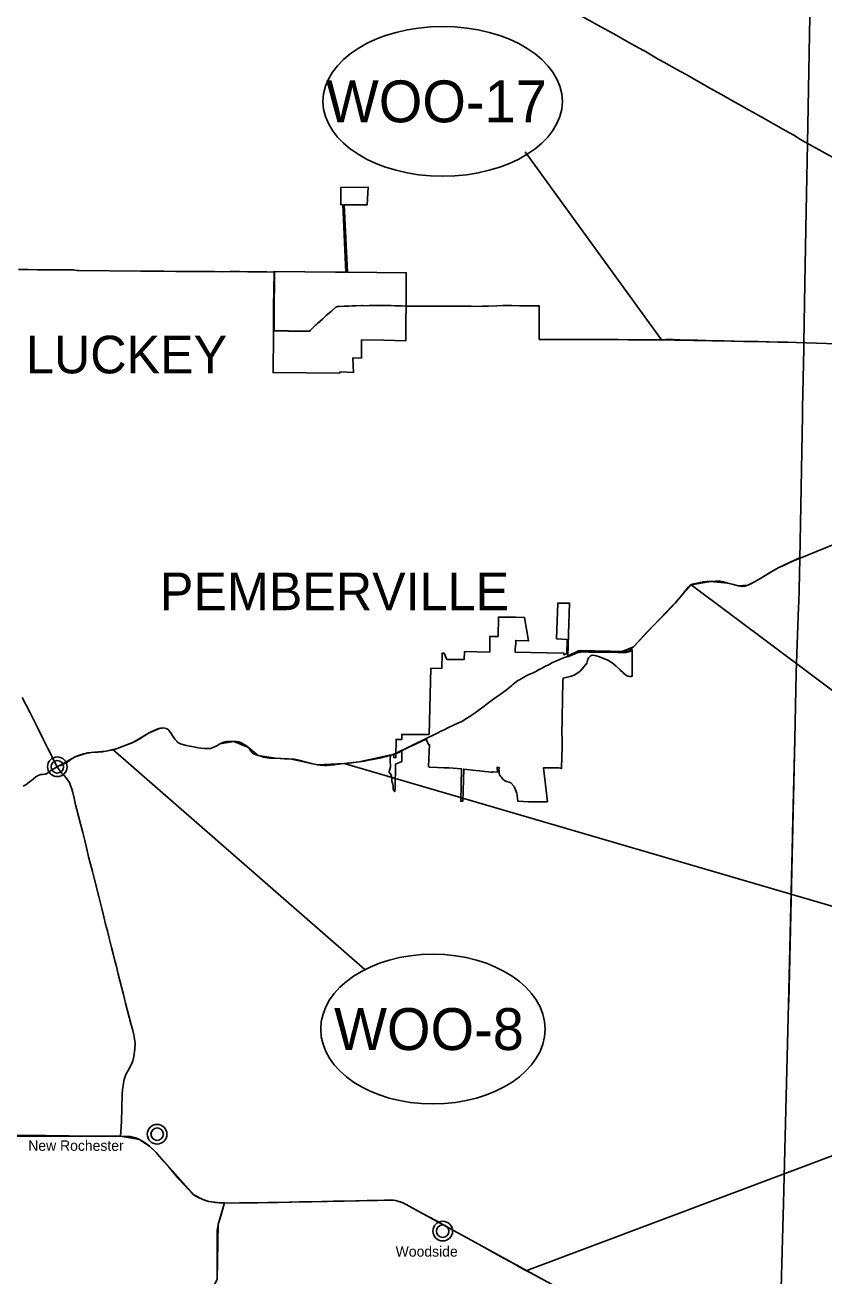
# Model space of a CAD drawing. Extents: x 0 to 851, y 0 to 440.
# Drawn here: x 370.6 to 424, y 193.8 to 277.3 of the extents above; entities that cross this region are included whole.
import ezdxf

# ---------------------------------------------------------------- set-up
doc = ezdxf.new("R2010")
doc.units = 0
for name, color, linetype in [('DV_X_Corp_Line', 7, 'Continuous'), ('GM_X_Corporation_Text', 7, 'Continuous'), ('GM_X_County', 7, 'Continuous'), ('GM_X_State_Route', 7, 'Continuous'), ('GM_X_US_Route', 7, 'Continuous'), ('RD_P_Fence', 7, 'Continuous'), ('SH_Data', 7, 'Continuous')]:
    doc.layers.add(name, color=color, linetype=linetype)

msp = doc.modelspace()

# ---------------------------------------------------------------- linework, layer by layer
at = {"layer": 'DV_X_Corp_Line'}
for points in [[(394.584, 256.284), (393.101, 256.305), (393.093, 255.09), (392.505, 255.087), (392.569, 254.126), (391.656, 254.156), (391.632, 254.084), (387.18, 254.12), (387.182, 254.462), (387.2, 256.317), (387.205, 256.909), (387.213, 257.407), (387.215, 258.013), (387.221, 258.556), (387.232, 259.629), (387.247, 260.871), (391.362, 260.823), (392.054, 260.821), (391.856, 265.336), (391.703, 265.333), (391.711, 266.479), (393.53, 266.511), (393.481, 265.331), (391.936, 265.327), (392.152, 260.82), (396.083, 260.785), (396.075, 258.565), (396.065, 257.568), (396.054, 256.234)], [(403.472, 226.002), (403.296, 226.461), (403.073, 226.7), (402.954, 226.741), (402.782, 226.8), (402.657, 226.868), (402.542, 226.952), (402.446, 227.075), (402.378, 227.159), (402.327, 227.248), (402.287, 227.357), (402.287, 227.479), (402.283, 227.593), (402.289, 227.702), (402.289, 227.737), (402.16, 227.742), (402.182, 227.412), (401.893, 227.448), (401.869, 227.435), (401.824, 227.422), (401.751, 227.417), (399.926, 227.616), (399.856, 225.475), (399.732, 225.476), (399.782, 227.631), (398.935, 227.703), (398.605, 227.712), (398.167, 227.737), (397.619, 227.753), (397.565, 227.806), (397.628, 229.258), (397.6, 229.229), (397.42, 229.61), (397.09, 229.456), (396.711, 229.281), (396.266, 229.076), (395.795, 228.858), (395.795, 228.131), (395.37, 227.945), (395.337, 226.34), (395.316, 226.114), (395.23, 226.243), (395.219, 226.304), (395.217, 226.403), (395.212, 226.488), (395.188, 226.582), (395.147, 226.75), (395.13, 226.792), (395.118, 226.862), (395.121, 226.964), (395.112, 227.056), (395.088, 227.153), (395.044, 227.252), (394.942, 227.409), (394.938, 227.456), (395.03, 227.77), (395.011, 228.213), (395.01, 228.253), (395.022, 228.541), (395.253, 228.62), (395.25, 228.386), (395.377, 228.382), (395.383, 228.671), (395.385, 228.738), (395.402, 229.351), (395.404, 229.602), (395.781, 229.598), (395.784, 229.934), (397.616, 229.94), (397.736, 234.359), (398.474, 234.351), (398.492, 235.373), (398.614, 235.369), (398.803, 234.952), (399.952, 234.941), (399.981, 235.488), (401.661, 235.432), (401.665, 235.65), (401.67, 236.49), (402.225, 236.485), (402.25, 237.778), (403.404, 237.762), (403.99, 237.742), (404.268, 236.182), (403.405, 236.223), (403.402, 236.024), (403.368, 235.628), (403.358, 235.438), (404.409, 235.409), (406.629, 235.372), (406.626, 235.252), (406.813, 235.346), (406.839, 236.291), (406.135, 236.314), (406.209, 238.708), (407.003, 238.71), (406.942, 236.669), (406.897, 235.121), (407.082, 235.203), (407.355, 235.327), (407.483, 235.381), (407.553, 235.406), (407.601, 235.419), (407.645, 235.432), (407.685, 235.434), (407.766, 235.442), (407.866, 235.445), (408.03, 235.445), (408.068, 235.445), (408.247, 235.442), (408.371, 235.441), (408.586, 235.438), (408.809, 235.436), (409.207, 235.434), (409.76, 235.431), (410.245, 235.421), (410.507, 235.416), (410.767, 235.419), (410.84, 235.428), (410.932, 235.451), (411.02, 235.487), (411.09, 235.527), (411.123, 235.551), (411.187, 235.607), (411.186, 235.43), (411.195, 234.342), (411.178, 233.827), (411.117, 233.811), (411.013, 233.811), (410.913, 233.833), (410.851, 233.849), (410.811, 233.869), (410.619, 234.016), (410.576, 234.07), (410.537, 234.116), (410.498, 234.14), (410.407, 234.216), (410.385, 234.254), (410.127, 234.502), (409.86, 234.713), (409.605, 234.867), (409.005, 235.126), (408.708, 235.202), (408.563, 235.233), (408.474, 235.218), (408.403, 235.183), (408.352, 235.14), (408.277, 235.047), (408.227, 234.949), (408.211, 234.902), (408.188, 234.799), (408.157, 234.709), (408.112, 234.623), (407.844, 234.314), (407.685, 234.137), (407.303, 233.902), (407.038, 233.803), (406.569, 233.686), (406.556, 233.498), (406.482, 229.852), (406.495, 229.836), (406.503, 229.82), (406.508, 229.797), (406.509, 229.763), (406.498, 229.081), (406.473, 227.728), (406.458, 227.654), (406.385, 227.691), (406.275, 227.702), (405.816, 227.703), (405.531, 227.701), (405.251, 227.7), (405.525, 225.438), (404.251, 225.44), (403.534, 225.482)]]:
    msp.add_lwpolyline(points, close=True, dxfattribs=at)
for centre, radius in [((372.759, 227.776), 0.658), ((372.759, 227.776), 0.417), ((379.429, 203.225), 0.658), ((379.429, 203.225), 0.417), ((398.524, 196.747), 0.658), ((398.524, 196.747), 0.417)]:
    msp.add_circle(centre, radius, dxfattribs=at)
at = {"layer": 'GM_X_County'}
for points in [[(423.071, 277.904), (422.913, 269.421), (422.829, 264.91), (422.736, 260.06), (422.663, 256.112), (422.656, 255.708), (422.581, 251.731), (422.571, 251.234), (422.414, 242.835), (422.393, 241.702), (422.354, 239.611), (422.324, 238.776), (422.312, 238.467), (422.154, 234.079), (422.051, 229.599), (421.95, 225.183), (421.908, 223.275)], [(421.906, 223.168), (421.647, 211.926), (421.534, 207.502), (421.3, 198.608), (421.066, 189.761)]]:
    msp.add_lwpolyline(points, dxfattribs=at)
at = {"layer": 'GM_X_State_Route'}
for points in [[(370.155, 260.998), (370.789, 260.993), (371.437, 260.99), (372.145, 260.987), (372.735, 260.983), (373.322, 260.979), (373.835, 260.973), (373.925, 260.962), (374.062, 260.944), (374.173, 260.938), (378.342, 260.896), (379.1, 260.891), (379.885, 260.886), (380.673, 260.88), (381.418, 260.872), (382.102, 260.87), (382.632, 260.867), (383.246, 260.862), (383.782, 260.853), (384.313, 260.861), (384.942, 260.864), (385.495, 260.855), (386.077, 260.856), (386.774, 260.851), (387.279, 260.836)], [(387.279, 260.836), (387.252, 258.001), (387.248, 256.906)], [(390.005, 257.251), (390.079, 257.322), (390.15, 257.388), (390.512, 257.718), (390.734, 257.919), (390.844, 258.014), (391.077, 258.215), (391.404, 258.501), (391.434, 258.518), (391.491, 258.53), (391.619, 258.538), (391.954, 258.553), (392.229, 258.562), (392.25, 258.563), (392.463, 258.571), (392.714, 258.577), (393.066, 258.588), (393.135, 258.587), (393.243, 258.585), (393.605, 258.589), (393.635, 258.59), (393.963, 258.59), (394.385, 258.593), (394.831, 258.596), (395.078, 258.596), (395.336, 258.585), (395.654, 258.573), (395.764, 258.568)], [(395.764, 258.568), (396.116, 258.555)], [(396.116, 258.555), (396.608, 258.557), (397.177, 258.554), (397.746, 258.555), (398.372, 258.552), (398.885, 258.55), (399.42, 258.544), (399.919, 258.543), (400.415, 258.545), (400.746, 258.54), (401.151, 258.55), (401.577, 258.563), (402.129, 258.577), (402.515, 258.588), (402.823, 258.593), (403.141, 258.594), (403.666, 258.582), (404.195, 258.577), (404.647, 258.576), (404.954, 258.568), (404.972, 258.567), (404.975, 257.997), (404.976, 257.283), (404.97, 256.716), (404.97, 256.337)], [(387.248, 256.906), (387.727, 256.898), (388.077, 256.895), (388.162, 256.895), (388.214, 256.893), (388.215, 256.893)], [(388.215, 256.893), (388.549, 256.891), (389.052, 256.887), (389.27, 256.888)], [(389.27, 256.888), (389.539, 256.889), (389.633, 256.892), (389.688, 256.946)], [(389.688, 256.946), (390.005, 257.251)], [(404.97, 256.337), (405.599, 256.334), (406.299, 256.329), (406.942, 256.329), (407.568, 256.322), (408.177, 256.318), (408.713, 256.316), (409.299, 256.317), (409.737, 256.316), (410.23, 256.315), (410.889, 256.311), (411.512, 256.304), (412.088, 256.311), (412.787, 256.313), (413.43, 256.316), (413.814, 256.315), (413.896, 256.315), (414.371, 256.3), (414.937, 256.288), (415.556, 256.271), (416.145, 256.258), (416.754, 256.248), (417.33, 256.232), (417.999, 256.217), (418.621, 256.2), (419.14, 256.192), (419.619, 256.184), (420.144, 256.172), (420.921, 256.152), (421.594, 256.141), (422.152, 256.129), (449.281, 255.224)], [(411.279, 235.8), (411.519, 236.062), (411.735, 236.299), (411.977, 236.554), (412.164, 236.762), (412.352, 236.953), (412.638, 237.237), (412.907, 237.508), (413.166, 237.772), (413.432, 238.039), (413.807, 238.432), (414.06, 238.706), (414.285, 238.971), (414.521, 239.259), (414.764, 239.57), (414.956, 239.791), (415.044, 239.887), (415.129, 239.943), (415.2, 239.975), (415.318, 240.007), (415.529, 240.054), (415.741, 240.097), (415.936, 240.137), (416.05, 240.142), (416.207, 240.15), (416.442, 240.163), (416.76, 240.167), (417.065, 240.176), (417.165, 240.164), (417.295, 240.128), (417.578, 240.053), (417.955, 239.95), (418.278, 239.864), (418.418, 239.838), (418.576, 239.832), (418.747, 239.853), (418.915, 239.901), (419.074, 239.968), (419.408, 240.151), (419.729, 240.337), (420.075, 240.552), (420.362, 240.732), (420.633, 240.889), (420.792, 240.976), (420.954, 241.058), (421.18, 241.165), (421.555, 241.336), (421.936, 241.514), (427.868, 243.947)], [(408.042, 235.514), (408.075, 235.511), (408.232, 235.505), (408.379, 235.5), (408.58, 235.503), (408.845, 235.505), (409.206, 235.506), (409.504, 235.504), (409.745, 235.504), (410.026, 235.486), (410.301, 235.475), (410.508, 235.471), (410.773, 235.48), (410.877, 235.495), (410.965, 235.531), (411.063, 235.6), (411.172, 235.695), (411.274, 235.794), (411.279, 235.8)], [(405.057, 234.315), (405.128, 234.352), (405.341, 234.47), (405.629, 234.616), (405.872, 234.733), (406.091, 234.84), (406.287, 234.93), (406.553, 235.033), (406.643, 235.069), (406.646, 235.07)], [(406.646, 235.07), (406.749, 235.11), (406.887, 235.178)], [(406.887, 235.178), (406.914, 235.192), (407.13, 235.295), (407.373, 235.402), (407.606, 235.512), (407.663, 235.528), (407.73, 235.537), (407.824, 235.532), (408.042, 235.514)], [(404.345, 233.97), (404.568, 234.056), (404.75, 234.144), (404.936, 234.252), (405.057, 234.315)], [(399.751, 230.778), (399.78, 230.791), (399.807, 230.808), (399.868, 230.847), (400.186, 231.046), (400.333, 231.141), (400.42, 231.197), (400.691, 231.373), (400.777, 231.438), (400.88, 231.516), (401.284, 231.816), (401.522, 232.003), (401.95, 232.309), (402.226, 232.514), (402.356, 232.61), (402.777, 232.919), (403.014, 233.106), (403.145, 233.214), (403.146, 233.214)], [(403.146, 233.214), (403.242, 233.293), (403.436, 233.455), (403.544, 233.53), (403.646, 233.588), (403.652, 233.592), (403.923, 233.742), (404.136, 233.869), (404.345, 233.97)], [(372.759, 227.776), (372.659, 227.936), (372.428, 228.395), (372.124, 228.997), (371.836, 229.582), (371.47, 230.306), (371.16, 230.925), (370.916, 231.415), (370.65, 231.945), (370.413, 232.408)], [(398.062, 229.976), (398.063, 229.976), (398.254, 230.072), (398.269, 230.079), (398.656, 230.27), (398.83, 230.351), (398.92, 230.393), (399.25, 230.548), (399.588, 230.704), (399.751, 230.778)], [(374.808, 228.702), (374.901, 228.712), (375.032, 228.726), (375.254, 228.741), (375.472, 228.756), (375.772, 228.785), (376.011, 228.813), (376.246, 228.855), (376.486, 228.913), (376.77, 228.997), (377.054, 229.101), (377.288, 229.193), (377.514, 229.281), (377.707, 229.357), (377.86, 229.424), (378.084, 229.536), (378.339, 229.692), (378.598, 229.857), (378.86, 230.015), (379.081, 230.134), (379.288, 230.233), (379.481, 230.306), (379.633, 230.346), (379.768, 230.366), (379.865, 230.371), (379.945, 230.359), (380.035, 230.333), (380.158, 230.26), (380.243, 230.187), (380.321, 230.064), (380.476, 229.825), (380.622, 229.627), (380.739, 229.476), (380.825, 229.394), (380.904, 229.351), (381.004, 229.309), (381.147, 229.262), (381.37, 229.199), (381.614, 229.15), (381.888, 229.099), (382.172, 229.049), (382.379, 229.02), (382.59, 229.005), (382.791, 228.994), (382.912, 228.994), (382.999, 229.006), (383.118, 229.046), (383.263, 229.103), (383.414, 229.183), (383.617, 229.312), (383.822, 229.399), (383.954, 229.438), (384.078, 229.459), (384.192, 229.474), (384.353, 229.475), (384.557, 229.465), (384.741, 229.455), (384.888, 229.439), (385.004, 229.407), (385.097, 229.358), (385.253, 229.259), (385.419, 229.159), (385.534, 229.059), (385.61, 228.974), (385.681, 228.863), (385.733, 228.775), (385.786, 228.717), (385.859, 228.658), (385.988, 228.589), (386.181, 228.522), (386.361, 228.476), (386.544, 228.422), (386.681, 228.39), (386.795, 228.375), (386.955, 228.359), (387.166, 228.352), (387.35, 228.349), (387.648, 228.331), (387.945, 228.316), (388.213, 228.301), (388.42, 228.291), (388.49, 228.285), (388.601, 228.275), (388.815, 228.244), (389.001, 228.198), (389.245, 228.13), (389.511, 228.065), (389.738, 228.005), (389.941, 227.951), (390.145, 227.914), (390.322, 227.888), (390.472, 227.875), (390.613, 227.866), (390.78, 227.867), (391.001, 227.883), (391.276, 227.912), (391.562, 227.945), (391.934, 227.989), (392.269, 228.027), (392.612, 228.072), (392.941, 228.116), (393.29, 228.161), (393.568, 228.21), (393.827, 228.253), (394.082, 228.312), (394.314, 228.362), (394.536, 228.416), (394.775, 228.462), (394.929, 228.502)], [(397.504, 229.699), (397.506, 229.7), (397.832, 229.861), (398.062, 229.976)], [(395.752, 228.825), (395.901, 228.9), (396.259, 229.078), (396.667, 229.283), (397.099, 229.497), (397.265, 229.58)], [(397.265, 229.58), (397.451, 229.672), (397.504, 229.699)], [(372.759, 227.776), (372.888, 227.84), (373.088, 227.916), (373.26, 227.992), (373.427, 228.086), (373.574, 228.196), (373.758, 228.326), (373.942, 228.43), (374.105, 228.506), (374.311, 228.572), (374.503, 228.631), (374.706, 228.69), (374.808, 228.702)], [(394.929, 228.502), (395.007, 228.522), (395.111, 228.564), (395.181, 228.584)], [(395.181, 228.584), (395.35, 228.634)], [(395.35, 228.634), (395.475, 228.685), (395.627, 228.763), (395.752, 228.825)], [(370.939, 226.8), (371.157, 226.981), (371.321, 227.108), (371.467, 227.189), (371.585, 227.236), (371.663, 227.254), (371.76, 227.259), (371.905, 227.272), (371.986, 227.29), (372.057, 227.322), (372.132, 227.378), (372.286, 227.495), (372.446, 227.599), (372.599, 227.689), (372.759, 227.776)], [(377.674, 210.621), (377.325, 211.982), (377.182, 212.566), (377.074, 212.975), (376.946, 213.485), (376.835, 213.921), (376.706, 214.425), (376.586, 214.891), (376.495, 215.27), (376.384, 215.696), (376.267, 216.145), (376.203, 216.402), (376.102, 216.811), (375.989, 217.267), (375.872, 217.74), (375.759, 218.21), (375.642, 218.656), (375.533, 219.116), (375.237, 220.252), (375.102, 220.786), (374.847, 221.763), (374.743, 222.185), (374.591, 222.844), (374.453, 223.388), (374.305, 223.953), (374.177, 224.466), (374.045, 224.984), (373.981, 225.234), (373.88, 225.683), (373.791, 226.051), (373.711, 226.345), (373.648, 226.525), (373.566, 226.718), (373.469, 226.879), (373.355, 227.029), (373.225, 227.197), (373.064, 227.359), (372.947, 227.489), (372.846, 227.636), (372.759, 227.776)], [(370.464, 226.48), (370.613, 226.557), (370.736, 226.632), (370.917, 226.782), (370.939, 226.8)], [(376.986, 203.089), (376.999, 203.389), (377.039, 204.078), (377.099, 205.891), (377.117, 206.183), (377.172, 206.632), (377.229, 206.872), (377.322, 207.143), (377.391, 207.305), (377.5, 207.487), (377.712, 207.894), (377.805, 208.133), (377.874, 208.408), (377.946, 208.897), (377.956, 209.288), (377.928, 209.599), (377.873, 209.866), (377.796, 210.144), (377.674, 210.621)], [(383.445, 195.693), (383.443, 196.597), (383.444, 196.791), (383.517, 197.183), (383.579, 197.423), (383.713, 197.843), (383.942, 198.631)], [(383.439, 193.781), (383.438, 194.182), (383.439, 194.723), (383.447, 195.203), (383.445, 195.693)], [(383.439, 193.729), (383.439, 193.781)]]:
    msp.add_lwpolyline(points, dxfattribs=at)
at = {"layer": 'GM_X_US_Route'}
for points in [[(404.973, 279.502), (405.167, 279.393), (405.375, 279.278), (406.232, 278.806), (406.883, 278.446), (407.37, 278.176), (408.856, 277.353), (410.162, 276.629)], [(410.162, 276.629), (410.38, 276.509), (411.17, 276.069)], [(411.17, 276.069), (411.944, 275.637)], [(411.944, 275.637), (411.959, 275.629), (412.935, 275.06), (413.309, 274.852), (413.665, 274.656), (414.025, 274.453), (414.429, 274.229), (414.84, 274), (415.331, 273.725), (415.741, 273.495), (416.221, 273.219), (416.677, 272.968), (417.118, 272.712), (417.477, 272.512), (417.852, 272.304), (418.285, 272.058), (418.538, 271.912), (418.959, 271.68), (419.295, 271.489), (419.618, 271.318), (420.018, 271.088), (420.44, 270.851), (420.837, 270.629), (421.26, 270.389), (421.67, 270.165), (422.03, 269.953), (422.401, 269.704), (431.143, 264.882)], [(421.906, 223.168), (421.65, 212.075), (422.051, 229.599), (422.154, 234.079), (422.312, 238.467), (422.324, 238.776), (422.354, 239.611), (422.393, 241.702), (422.414, 242.835), (422.571, 251.234), (422.581, 251.731), (422.656, 255.708), (422.663, 256.112), (422.736, 260.06), (422.829, 264.91), (422.913, 269.421)], [(421.066, 189.761), (421.066, 189.761), (421.3, 198.608), (421.534, 207.502), (421.647, 211.926), (421.65, 212.075)], [(367.677, 203.144), (371.958, 203.137), (376.653, 203.074), (376.986, 203.089)], [(376.986, 203.089), (377.227, 203.081), (377.44, 203.077), (377.648, 203.062), (377.825, 203.027), (378.009, 202.978), (378.255, 202.865), (378.484, 202.741), (378.709, 202.591), (378.946, 202.393), (379.192, 202.175), (379.376, 201.993), (379.591, 201.742), (379.898, 201.374), (380.231, 200.99), (380.563, 200.588), (380.88, 200.227), (381.217, 199.862), (381.518, 199.525), (381.773, 199.26), (381.875, 199.17), (381.981, 199.104), (382.117, 199.03), (382.276, 198.952), (382.343, 198.923), (382.496, 198.855), (382.719, 198.782), (382.876, 198.728), (383.075, 198.703), (383.308, 198.668), (383.445, 198.652), (383.552, 198.643), (383.676, 198.633), (383.942, 198.631)], [(383.942, 198.631), (384.381, 198.624), (384.966, 198.632), (385.527, 198.636), (386.152, 198.646), (386.831, 198.658), (387.506, 198.67), (388.249, 198.684), (388.954, 198.695), (389.771, 198.714), (390.43, 198.723), (391.199, 198.74), (391.945, 198.76), (392.722, 198.774), (393.474, 198.787), (394.156, 198.799), (394.628, 198.807), (394.677, 198.808), (395.044, 198.82), (395.238, 198.816), (395.366, 198.8), (395.526, 198.759), (395.699, 198.705), (395.866, 198.634), (396.032, 198.547), (396.367, 198.361), (396.795, 198.127), (397.207, 197.903), (397.635, 197.672), (398.053, 197.448), (398.578, 197.161), (399.039, 196.912), (399.447, 196.678), (399.775, 196.499), (399.882, 196.441), (400.469, 196.115), (400.951, 195.846), (401.508, 195.542), (402.029, 195.252), (402.587, 194.947), (403.101, 194.664), (403.389, 194.507), (403.523, 194.433), (404.041, 194.15), (404.525, 193.884), (405.126, 193.558)]]:
    msp.add_lwpolyline(points, dxfattribs=at)
at = {"layer": 'RD_P_Fence'}
for points in [[(421.594, 256.141), (412.787, 256.313), (404.97, 256.337)], [(407.73, 235.537), (410.508, 235.471), (411.274, 235.794), (412.638, 237.237), (414.285, 238.971), (415.129, 239.943), (416.442, 240.163), (417.578, 240.053), (418.278, 239.864), (418.915, 239.901), (419.408, 240.151), (420.954, 241.058), (422.463, 241.771)], [(372.446, 227.599), (373.942, 228.43), (374.808, 228.702), (376.011, 228.813), (376.77, 228.997), (377.86, 229.424), (378.86, 230.015), (379.633, 230.346)], [(383.617, 229.312), (384.557, 229.465), (385.534, 229.059), (386.181, 228.522), (387.35, 228.349), (388.42, 228.291), (390.145, 227.914), (391.934, 227.989), (392.941, 228.116), (395.271, 228.615), (397.506, 229.7)], [(317.186, 195.649), (318.84, 195.642), (321.175, 195.867), (324.217, 196.452), (326.17, 196.864), (327.965, 197.248), (329.959, 197.627), (331.901, 197.495), (336.758, 197.369), (339.671, 197.295), (342.121, 197.516), (344.613, 198.402), (347.617, 200.166), (350.381, 201.846), (352.244, 202.906), (353.784, 203.3), (355.119, 203.306), (356.974, 203.158), (358.476, 203.099), (368.358, 203.099), (376.986, 203.089)], [(412.096, 189.896), (411.575, 190.049), (396.032, 198.547), (395.866, 198.634), (395.526, 198.759), (395.366, 198.8), (395.044, 198.82), (389.771, 198.714), (384.381, 198.624), (383.676, 198.633), (382.876, 198.728), (382.496, 198.855), (381.875, 199.17), (379.376, 201.993), (378.946, 202.393), (378.255, 202.865), (376.986, 203.089)], [(385.822, 132.188), (383.381, 138.251), (381.593, 142.391), (380.119, 147.573), (378.801, 153.153), (378.173, 155.941), (378.091, 161.6), (378.2, 165.175), (380.52, 168.801), (380.716, 174.784), (383.427, 177.972), (385.007, 180.01), (385.39, 182.891), (385.181, 184.857), (382.636, 189.058), (382.184, 191.21), (383.44, 193.511), (383.517, 197.183), (383.942, 198.631)]]:
    msp.add_lwpolyline(points, dxfattribs=at)
at = {"layer": 'SH_Data'}
for p, q in [((404.043, 268.856), (413.154, 256.306)), ((428.087, 230.225), (415.129, 239.943)), ((393.314, 214.221), (376.462, 228.922)), ((427.531, 217.593), (391.934, 227.989)), ((428.53, 203.27), (404.136, 194.116))]:
    msp.add_line(p, q, dxfattribs=at)
for centre, major_axis, ratio in [((398.519, 272.237), (8, 0), 0.625), ((397.868, 210.248), (7.5, 0), 0.666667)]:
    msp.add_ellipse(centre, major_axis=major_axis, ratio=ratio, dxfattribs=at)

# ---------------------------------------------------------------- texts
at = {"layer": 'DV_X_Corp_Line'}
for s, height, p in [('New Rochester', 0.69792, (370.814, 202.114)), ('Woodside', 0.6979, (395.375, 195.041))]:
    msp.add_text(s, height=height, rotation=0.00001, dxfattribs=at).set_placement(p)
at = {"layer": 'GM_X_Corporation_Text'}
for s, height, p in [('LUCKEY', 2.5126, (370.665, 254.064)), ('PEMBERVILLE', 2.51255, (379.615, 238.24))]:
    msp.add_text(s, height=height, rotation=0.00001, dxfattribs=at).set_placement(p)
at = {"layer": 'SH_Data'}
for s, p in [('WOO-17', (390.714, 270.837)), ('WOO-8', (391.262, 208.848))]:
    msp.add_text(s, height=2.8, dxfattribs=at).set_placement(p)

doc.saveas('drawing.dxf')
